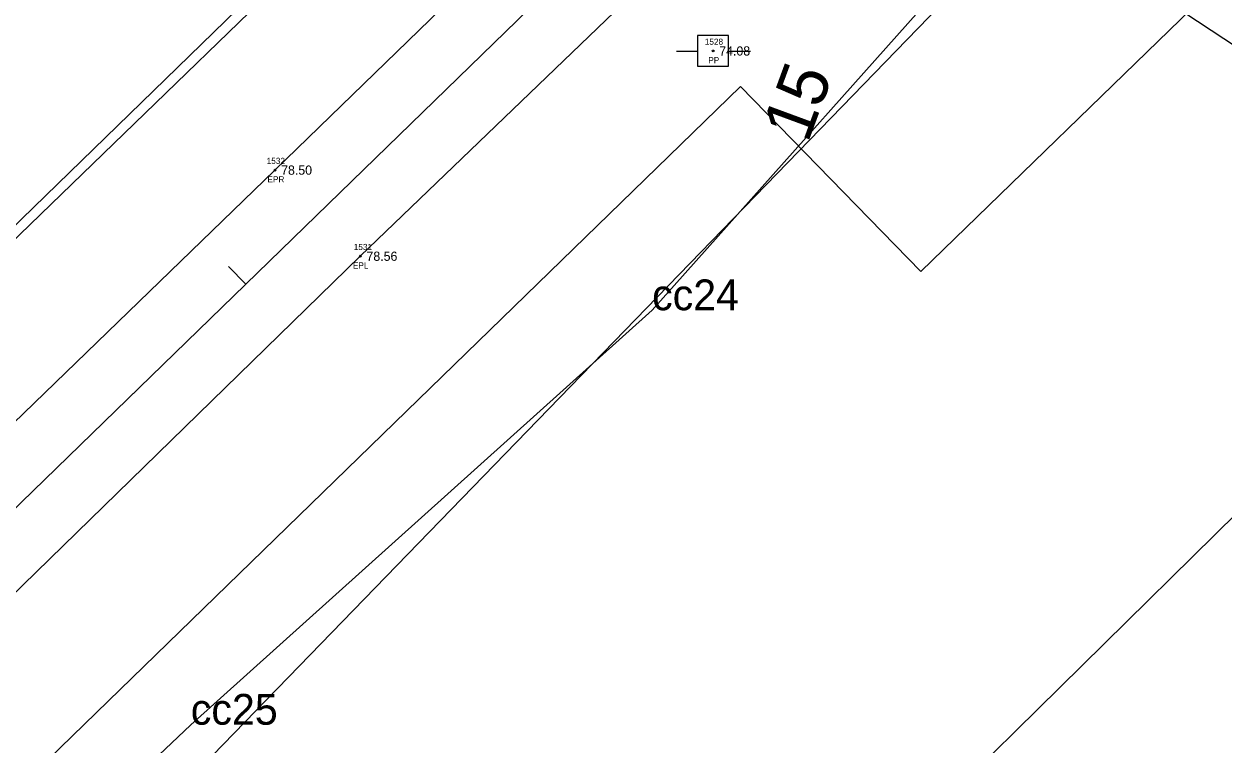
# Model space of a CAD drawing. Extents: x 2500794 to 2511032, y 910653 to 917533.
# Drawn here: x 2505136.3 to 2505331.2, y 912787.9 to 912905 of the extents above; entities that cross this region are included whole.
import ezdxf

# ---------------------------------------------------------------- set-up
doc = ezdxf.new("R2010")
doc.units = 0
for name, color, linetype in [('Default', 7, 'Continuous'), ('RD_EX_DV_Prop', 7, 'Continuous'), ('RD_EX_H2O_txCode', 7, 'Continuous'), ('RD_EX_H2O_WetLd', 7, 'Continuous'), ('RD_EX_Road', 7, 'Continuous'), ('RD_EX_Road_txCode', 7, 'Continuous'), ('RD_EX_RW', 7, 'Continuous'), ('RD_EX_TX_Road_ELEV', 7, 'Continuous'), ('RD_EX_UT', 7, 'Continuous'), ('RD_EX_UT_txCode', 7, 'Continuous'), ('RD_EX_VEG', 7, 'Continuous'), ('RD_HC_Cl', 7, 'Continuous'), ('RD_HC_Data_Tic', 7, 'Continuous'), ('RD_HC_Survey_ELEV', 7, 'Continuous'), ('RD_HC_TX_Sta50', 7, 'Continuous'), ('RD_SMD_Locator', 7, 'Continuous')]:
    doc.layers.add(name, color=color, linetype=linetype)

# ---------------------------------------------------------------- blocks, each defined once
blk = doc.blocks.new('POINT_DISPLAY')
at = {"layer": 'Default'}
blk.add_line((0, 0), (0, 0), dxfattribs=at)
blk = doc.blocks.new('Wetlands')
at = {"layer": 'Default'}
blk.add_lwpolyline([(636373.86, 231876.593), (636322.695, 231826.15), (636292.001, 231795.727), (636288.552, 231801.204), (636276.275, 231810.411), (636280.758, 231816.983), (636294.104, 231832.432), (636311.497, 231848.926), (636330.531, 231866.041), (636344.713, 231881.969), (636343.035, 231887.6), (636348.3, 231893.346), (636354.376, 231887.946)], dxfattribs=at)

msp = doc.modelspace()

# ---------------------------------------------------------------- linework, layer by layer
at = {"layer": 'RD_EX_DV_Prop'}
msp.add_line((2503534.53, 911315.65), (2505206.65, 912942.11), dxfattribs=at)
at = {"layer": 'RD_EX_H2O_txCode'}
msp.add_lwpolyline([(2505244.66, 912978.18), (2505259.72, 912972.49), (2505282.9, 912947.05), (2505291.19, 912934.61), (2505301.24, 912922.37), (2505337.69, 912898.33), (2505350.73, 912862.58), (2505336.39, 912800.89), (2505361.15, 912786.5), (2505403.95, 912734.79), (2505467.35, 912720.29), (2505522.39, 912682.34)], dxfattribs=at)
at = {"layer": 'RD_EX_Road'}
for points in [[(2505356.25, 913055.37), (2505297.36, 912998.59), (2505254.44, 912956.44), (2505177.06, 912881.21), (2505102.21, 912808.73), (2505026.72, 912735.2), (2504956.07, 912666.21), (2504882.83, 912595.14), (2504825.46, 912547.52), (2504807.83, 912522.24), (2504732.55, 912448.69), (2504654.06, 912372.59), (2504585.1, 912305.45), (2504533.51, 912254.98)], [(2505370.6, 913041.78), (2505311.87, 912984.11), (2505268.01, 912941.43), (2505190.92, 912867.21), (2505116.28, 912794.43), (2505039.14, 912719.03), (2504973.12, 912654.77), (2504957.32, 912639.49), (2504897.44, 912581.22), (2504858.98, 912543.75), (2504838.29, 912523.7), (2504810.7, 912496.65), (2504795.8, 912482.32), (2504747.07, 912434.9), (2504696.6, 912386.17), (2504686.81, 912376.67), (2504668.39, 912358.37), (2504598.36, 912290.29), (2504547.08, 912240.34)]]:
    msp.add_lwpolyline(points, dxfattribs=at)
at = {"layer": 'RD_EX_RW'}
for p, q in [((2505281.96, 912864.7), (2505425.33, 913004.15)), ((2504517.34, 912271.63), (2505206.66, 912942.12)), ((2503981.18, 911658.03), (2505252.68, 912894.81)), ((2505281.96, 912864.7), (2505252.68, 912894.81))]:
    msp.add_line(p, q, dxfattribs=at)
at = {"layer": 'RD_EX_UT'}
for p, q in [((2505250.71, 912903.09), (2505245.71, 912903.09)), ((2505245.71, 912903.09), (2505245.71, 912898.09)), ((2505250.71, 912898.09), (2505250.71, 912903.09)), ((2505242.28, 912900.52), (2505245.74, 912900.52)), ((2505250.64, 912900.52), (2505254.28, 912900.52)), ((2505245.71, 912898.09), (2505250.71, 912898.09))]:
    msp.add_line(p, q, dxfattribs=at)
at = {"layer": 'RD_EX_VEG'}
for points in [[(2505339.13, 913074.53), (2505242.44, 912974.3), (2505088.02, 912824.67), (2504935.82, 912672.7), (2504815.59, 912550.95), (2504817.4, 912591.81)], [(2505299.12, 912922.5), (2505143.93, 912762.37), (2505067.63, 912689.26), (2504988.4, 912634.77), (2505004.57, 912602.97)]]:
    msp.add_lwpolyline(points, dxfattribs=at)
at = {"layer": 'RD_HC_Cl'}
msp.add_line((2504540.35, 912247.97), (2505598.79, 913277.5), dxfattribs=at)
at = {"layer": 'RD_HC_Data_Tic'}
msp.add_line((2505172.32, 912862.68), (2505169.53, 912865.55), dxfattribs=at)
at = {"layer": 'RD_SMD_Locator'}
for centre in [(2505248.22, 912900.58), (2505177.06, 912881.21), (2505190.92, 912867.21)]:
    msp.add_circle(centre, 0.15, dxfattribs=at)

# ---------------------------------------------------------------- block references
at = {"layer": 'Default', "xscale": 3.937007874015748, "yscale": 3.937007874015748}
for name, p in [('Wetlands', (0, 0)), ('POINT_DISPLAY', (2505238.31, 912858.43)), ('POINT_DISPLAY', (2505238.31, 912858.43)), ('POINT_DISPLAY', (2505163.38, 912791.05)), ('POINT_DISPLAY', (2505163.38, 912791.05))]:
    msp.add_blockref(name, p, dxfattribs=at)
at = {"layer": 'RD_EX_H2O_WetLd', "xscale": 3.937007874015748, "yscale": 3.937007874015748}
msp.add_blockref('Wetlands', (0, 0), dxfattribs=at)

# ---------------------------------------------------------------- texts
at = {"layer": 'Default'}
for s, p in [('cc24', (2505238.31, 912858.43)), ('cc24', (2505238.31, 912858.43)), ('cc25', (2505163.38, 912791.05)), ('cc25', (2505163.38, 912791.05))]:
    msp.add_text(s, height=5, dxfattribs=at).set_placement(p)
at = {"layer": 'RD_EX_Road_txCode'}
for s, p in [('1532', (2505175.71, 912882.21)), ('EPR', (2505175.83, 912879.21)), ('1531', (2505189.85, 912868.21)), ('EPL', (2505189.71, 912865.21))]:
    msp.add_text(s, height=1, dxfattribs=at).set_placement(p)
at = {"layer": 'RD_EX_TX_Road_ELEV'}
for s, p in [('78.50', (2505178.06, 912880.46)), ('78.56', (2505191.92, 912866.46))]:
    msp.add_text(s, height=1.5, dxfattribs=at).set_placement(p)
at = {"layer": 'RD_EX_UT_txCode'}
for s, p in [('1528', (2505246.87, 912901.58)), ('PP', (2505247.44, 912898.58))]:
    msp.add_text(s, height=1, dxfattribs=at).set_placement(p)
at = {"layer": 'RD_HC_Survey_ELEV'}
msp.add_text('74.08', height=1.5, dxfattribs=at).set_placement((2505249.22, 912899.83))
at = {"layer": 'RD_HC_TX_Sta50'}
msp.add_text('15', height=8, rotation=69.7477, dxfattribs=at).set_placement((2505263.57, 912885.44))

doc.saveas('drawing.dxf')
